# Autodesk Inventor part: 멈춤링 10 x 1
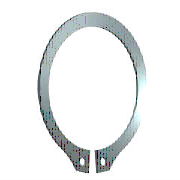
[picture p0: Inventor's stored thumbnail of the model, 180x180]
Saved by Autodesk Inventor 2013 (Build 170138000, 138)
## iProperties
IsCustomPart: 0
Company: 한국ATC센터
Created: 2009-02
Part Number: 멈춤링 10 x 1
Material: Steel, Mild
Description: 리테이닝 링(C형)
Document SubType Name: Modeling
Standard: KS B 1336
Designer: KYOUNG IL JANG
Standards Organization: KS
Language: ko-KR
Size Designation: 10 x 1
Categories: <MemberInstance><Categories><Category DisplayName="샤프트 부품" InternalName="7f7aeb1f-a693-4053-b835-cee3144e0d98" Mnemonic="SHFT"><Category DisplayName="써클립" Inter
Density: 7.86 g/cm^3
Mass: 0.423087 g
Surface Area: 1.9243 cm^2
Volume: 0.0538279 cm^3
Author: KYOUNG IL JANG
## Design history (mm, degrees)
sketch "스케치1"
  geometry: L1 (-6, 0)-(6, 0) reference; L2 (0, 20.189)-(0, -80.536) reference; L3 (-48.09, 0)-(48.09, 0) reference; L4 (-0.3, -9.791)-(-0.3, -12.791); L5 (-0.3, -6.54)-(-0.3, -13.29); L6 (-2.795, 1.6)-(3.672, 1.6); L7 (0.3, -6.54)-(0.3, -13.29); L8 (0.3, -9.791)-(0.3, -12.791); C1 r 0.6 at (-1.2, -11.486); C2 r 0.6 at (1.2, -11.486); A1 r 4.8 centre (0, -5) between (0.3, -9.791) and (-0.3, -9.791); A2 r 6.2 centre (0, -4.6) between (2.988, -10.033) and (-2.988, -10.033); A3 r 7.796 centre (0, -5) between (-1.418, -12.666) and (-0.3, -12.791); A4 r 1.2 centre (-1.2, -11.486) between (-2.383, -11.285) and (-1.418, -12.666); A5 r 1.2 centre (-3.566, -11.084) between (-2.383, -11.285) and (-2.988, -10.033); A6 r 1.2 centre (3.566, -11.084) between (2.988, -10.033) and (2.383, -11.285); A7 r 1.2 centre (1.2, -11.486) between (1.418, -12.666) and (2.383, -11.285); A8 r 7.796 centre (0, -5) between (0.3, -12.791) and (1.418, -12.666)
  constraints: 16 point on circle, 12 end point, 10 centre point, 9 symmetric about line, 5 point on line, 4 tangent, 3 coincident, 2 horizontal, 1 perpendicular, 1 vertical, 5 other
  dimensions: "d0" = 9.6 diameter of A1 (= ND); "d1" = 3 distance of L4.end L4.start (= SRB2); "d6" = 0.3 distance between parallel lines of L2 L5 (= 0.25 x SD5); "d7" = 1.6 distance between parallel lines of L6 L3 (= SRB1); "d8" = 0.4 distance of A1.centre A2.centre (= 0.25 x SRB1); "d9" = 1.2 radius of A4 (= SD5); "d10" = 1.2 radius of A5 (= SD5); "d11" = 0.9 distance from line of L4 A4.centre (= 0.75 x SD5); "d12" = 1.2 diameter of C1 (= SD5); "d13" = 1.2 diameter of C2 (= SD5); "d14" = 5 distance from line of A1.centre L1 (= 0.5 x WD)
extrude "본체" new body sketch "스케치1" distance "d2" = 1 (= SD); taper "d3" = 0 deg
workaxis "Work Axis1"
workplane "Work Plane1"
body "Solid1"
other parameters: "SD" = 1 [user parameter; used in 1 equation term], "SRB1" = 1.6 [user parameter; used in 2 equation terms], "ND" = 9.6 [user parameter; used in 1 equation term], "SRB2" = 3 [user parameter; used in 1 equation term], "SD5" = 1.2 [user parameter; used in 6 equation terms], "d15" = 0, "d16" = 0, "d17" = 0, "d41" = 0, "d42" = 0, "SD3" = 9.3 [user parameter], "WDMAX" = 11 [user parameter]
